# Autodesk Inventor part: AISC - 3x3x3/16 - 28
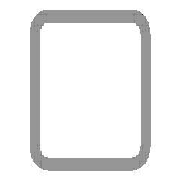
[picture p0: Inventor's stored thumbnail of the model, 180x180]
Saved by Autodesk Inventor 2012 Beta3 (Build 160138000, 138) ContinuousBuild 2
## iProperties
_CCFamilyMember: 9
_CCFamilyDisplayName: ANSI AISC (Square) - Tube
_FrameMemberDoc: Frame Member File
_Version: 15.0.0
_GetPNFromCC: 1
Created: 2011-01
Part Number: AISC - 3x3x3/16 - 28
Material: Steel, Mild
Description: Tube
Document SubType Name: Modeling
Standard: ANSI
Designer: Beta-8540w
Standards Organization: ANSI
Language: en-US
Size Designation: 3x3x3/16
Categories: <MemberInstance><Categories><Category DisplayName="Structural Shapes" InternalName="089c4875-fa83-4c05-b084-43b9cc11f5ed" Mnemonic="GRDR"><CategoryParameter Dis
Stock Number: 3x3x3/16
Density: 7.86 g/cm^3
IsCustomPart: 1
G_L: 28.000 in
G_W: 3.000 in
G_H: 3.000 in
Author: Beta-8540w
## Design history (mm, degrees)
node "Start plane"
node "End plane"
sketch "Sketch"
  geometry: L1 (-38.1, -28.575)-(-38.1, 28.575); L2 (-28.575, 38.1)-(28.575, 38.1); L3 (38.1, 28.575)-(38.1, -28.575); L4 (28.575, -38.1)-(-28.575, -38.1); L5 (-28.575, 33.337)-(28.575, 33.338); L6 (33.338, 28.575)-(33.338, -28.575); L7 (28.575, -33.337)-(-28.575, -33.338); L8 (-33.338, -28.575)-(-33.338, 28.575); L9 (0, 56.102)-(0, -56.102) reference; L10 (-56.102, 0)-(56.102, 0) reference; A1 r 9.525 centre (-28.575, -28.575) between (-38.1, -28.575) and (-28.575, -38.1); A2 r 9.525 centre (-28.575, 28.575) between (-28.575, 38.1) and (-38.1, 28.575); A3 r 9.525 centre (28.575, 28.575) between (38.1, 28.575) and (28.575, 38.1); A4 r 9.525 centre (28.575, -28.575) between (28.575, -38.1) and (38.1, -28.575); A5 r 4.763 centre (-28.575, 28.575) between (-28.575, 33.337) and (-33.338, 28.575); A6 r 4.763 centre (28.575, 28.575) between (33.338, 28.575) and (28.575, 33.338); A7 r 4.763 centre (28.575, -28.575) between (28.575, -33.337) and (33.338, -28.575); A8 r 4.763 centre (-28.575, -28.575) between (-33.338, -28.575) and (-28.575, -33.338)
  constraints: 16 end point, 16 point on circle, 8 centre point, 8 tangent, 4 parallel, 3 equal radius, 2 perpendicular, 7 other
  dimensions: "d10" = 76.2 distance between parallel lines of L2 L4 (= G_H); "d11" = 76.2 distance between parallel lines of L1 L3 (= G_W); "d12" = 4.7625 distance between parallel lines of L3 L6 (= G_T); "d15" = 38.1 distance between parallel lines of L2 L10 (= 0.5 x d10); "d16" = 38.1 distance between parallel lines of L9 L3 (= 0.5 x d11); "d17" = 9.525 radius of A1 (= G_IR)
extrude "Body" new body sketch "Sketch" stored distance "d3" = 711.2 (= G_L); taper "d4" = 0 deg
node "Driven Length"
  sketch "Sketch3"
    geometry: L1 (0, 0)-(10, 0) reference
    constraints: 2 end point, 1 horizontal
  workplane "Work Plane3"
  sketch "Sketch4"
    geometry: L1 (-2, 0)-(12, 0) reference; L2 (-2, 711.2)-(12, 711.2) reference
    dimensions: "d19" = 711.2 distance between parallel lines of L1 L2 (derived)
body "Solid1"
other parameters: "G_W" = 76.2 [user parameter; used in 1 equation term], "G_H" = 76.2 [user parameter; used in 1 equation term], "G_T" = 4.7625 [user parameter; used in 1 equation term], "G_IR" = 9.525 [user parameter; used in 1 equation term], "G_L" = 711.2 (= d19) [user parameter; used in 1 equation term], "G_OFFSET_START" = 0 [user parameter; used in 1 equation term], "G_OFFSET_END" = 0 [user parameter; used in 1 equation term], "d13" = 0 (computed from G_OFFSET_START), "d14" = 711.2 (= G_OFFSET_END + B_L), "B_L" = 711.2 [user parameter; used in 1 equation term], "d18" = 90 deg
